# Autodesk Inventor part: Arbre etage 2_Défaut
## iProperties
Shininess: 64.0
Length Units: 11269
Angle Units: 11279
Time Units: 11290
Mass Units: 11283
Length Display Precision: 3
Angle Display Precision: 2
Compacted: True
Part Number: Arbre etage 2_Défaut
Document SubType Name: Modeling
Created: 2006-01
Material: Par défaut
Designer: Fricot
Density: 0.0
Volumn: 0.0
Area: 0.0
PropertySet Name: Model Information
Control State: 0
Master: False
Checked Out: False
Author: Fricot
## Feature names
1. Base1
